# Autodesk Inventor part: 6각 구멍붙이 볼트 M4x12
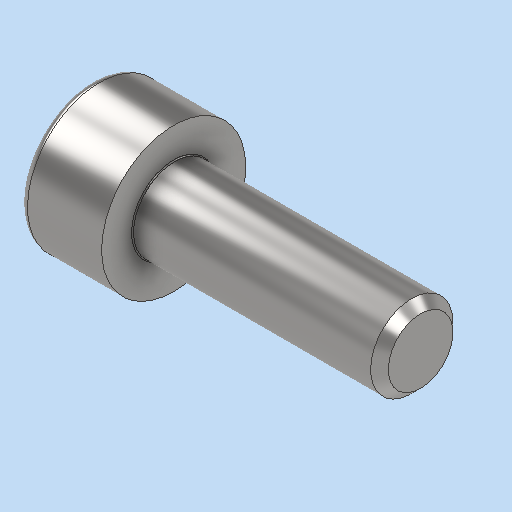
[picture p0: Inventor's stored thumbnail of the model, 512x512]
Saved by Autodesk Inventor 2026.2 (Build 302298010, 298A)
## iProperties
Created: 2026-04
Part Number: 6각 구멍붙이 볼트 M4x12
Material: 강철, 연강
Description: 6각머리 태핑 나사
Document SubType Name: Modeling
Designer: PC-2-06
Density: 7.85 g/cm^3
Appearance: 기본값
Author: jhkim
Sending System: Autodesk Inventor 2027
Preprocessor: ST-DEVELOPER v20.1
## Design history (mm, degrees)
feature "Solid1"
node "솔리드1"
